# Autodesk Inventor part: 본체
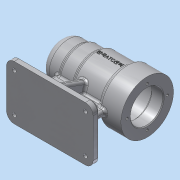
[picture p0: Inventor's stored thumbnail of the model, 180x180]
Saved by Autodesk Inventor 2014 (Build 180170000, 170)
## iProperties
Created: 2016-06
Part Number: 본체
Material: 알루미늄 6061
Document SubType Name: Modeling
Designer: 406-017
Density: 2.71 g/cm^3
Appearance: 알루미늄 - 평지
Mass: 624.755 g
Surface Area: 673.705 cm^2
Volume: 230.537 cm^3
Author: 406-017
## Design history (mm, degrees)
sketch "스케치1"
  geometry: L1 (0, 0)-(0, 25); L2 (0, 25)-(25, 25); L3 (25, 25)-(25, 27); L4 (25, 27)-(45, 27); L5 (45, 27)-(45, 30); L6 (45, 30)-(84, 30); L7 (84, 30)-(84, 34); L8 (84, 34)-(112, 34); L9 (112, 34)-(112, 0); L10 (112, 0)-(0, 0)
  constraints: 20 end point, 6 parallel, 2 perpendicular, 2 vertical
  dimensions: "d0" = 112 distance between parallel lines of L9 L1; "d1" = 50 diameter of L2 L10; "d2" = 54 diameter of L4 L10; "d4" = 60 diameter of L6 L10; "d5" = 68 diameter of L8 L10; "d6" = 25 distance of L1.end L2.end; "d7" = 45 distance between parallel lines of L5 L1; "d8" = 84 distance between parallel lines of L7 L1
revolve "회전1" sketch "스케치1" stored, may be unused: angle "d9" = 90 deg
sketch "스케치2"
  geometry: L1 (25, -25)-(0, -25) reference; L2 (0, -25)-(0, 25) reference; L3 (0, 25)-(25, 25) reference; L4 (25, 25)-(25, 27) reference; L5 (25, 27)-(45, 27) reference; L6 (45, 27)-(45, 30) reference; L7 (45, 30)-(84, 30) reference; L8 (84, 30)-(84, 34) reference; L9 (84, 34)-(112, 34) reference; L10 (112, 34)-(112, -34) reference; L11 (112, -34)-(84, -34) reference; L12 (84, -34)-(84, -30) reference; L13 (84, -30)-(45, -30) reference; L14 (45, -30)-(45, -27) reference; L15 (45, -27)-(25, -27) reference; L16 (25, -27)-(25, -25) reference; L17 (0, 0)-(112, 0); L18 (6, 0)-(6, 10.5); L19 (6, 10.5)-(9, 10.5); L20 (9, 10.5)-(9, 15.7); L21 (9.3, 16)-(13, 16); L22 (13, 16)-(13, 17.2); L23 (13.3, 17.5)-(31, 17.5); L24 (31, 17.5)-(31, 20.7); L25 (31.3, 21)-(43, 21); L26 (43, 21)-(43, 21); L27 (46, 24)-(94, 24); L28 (97, 21)-(97, 21); L29 (97, 21)-(112, 21); L30 (112, 0)-(112, 21); A1 r 0.3 centre (9.3, 15.7) between (9.3, 16) and (9, 15.7); A2 r 0.3 centre (13.3, 17.2) between (13.3, 17.5) and (13, 17.2); A3 r 0.3 centre (31.3, 20.7) between (31.3, 21) and (31, 20.7); A4 r 3 centre (46, 21) between (46, 24) and (43, 21); A5 r 3 centre (94, 21) between (97, 21) and (94, 24); 5 further points
  constraints: 28 end point, 12 point on line, 10 point on circle, 10 tangent, 6 perpendicular, 5 centre point, 5 parallel, 2 equal radius, 1 collinear, 1 midpoint, 1 vertical
  dimensions: "d10" = 15 distance of L28.end L29.end; "d11" = 54 distance of point (43, 24) point (97, 24); "d12" = 42 diameter of L29 L17; "d13" = 48 diameter of L27 L17; "d14" = 12 distance of point (31, 21) L25.end; "d15" = 18 distance of point (13, 17.5) L23.end; "d16" = 4 distance of point (9, 16) L21.end; "d17" = 3 distance of L18.end L19.end; "d18" = 42 diameter of L25 L17; "d19" = 35 diameter of L23 L17; "d20" = 32 diameter of L21 L17; "d21" = 21 diameter of L19 L17; "d22" = 0.3 radius of A1; "d50" = 3 radius of A4; "d85" = 3 radius of A5
revolve "회전2" sketch "스케치2" stored, may be unused: angle "d23" = 90 deg
node "작업 평면1"
sketch "스케치3"
  geometry: L1 (-112, -35)-(0, -35); L2 (0, -35)-(0, 35); L3 (0, 35)-(-112, 35); L4 (-112, 35)-(-112, -35); L5 (-112, -35)-(0, 35); L6 (0, -35)-(-112, 35); 2 further points
  constraints: 12 end point, 2 midpoint, 2 parallel, 1 horizontal, 1 perpendicular, 1 vertical alignment
  dimensions: "d25" = 112 distance of L2.end L3.end; "d26" = 70 distance of L1.end L2.end; "d27" = 35 distance from line of point (0, 0) L3
extrude "돌출1" join sketch "스케치3" distance "d28" = 10; taper "d29" = 0 deg
sketch "스케치4"
  geometry: L1 (92, -34)-(92, -60); L2 (92, -60)-(20, -60); L3 (20, -60)-(20, -27); L4 (20, -27)-(92, -60); L5 (92, -27)-(20, -60); L6 (112, -70)-(112, -60) reference; L7 (25, -25)-(0, -25) reference; L8 (0, -25)-(0, 25) reference; L9 (0, 25)-(25, 25) reference; L10 (25, 25)-(25, 27) reference; L11 (25, 27)-(45, 27) reference; L12 (45, 27)-(45, 30) reference; L13 (45, 30)-(84, 30) reference; L14 (84, 30)-(84, 34) reference; L15 (84, 34)-(112, 34) reference; L16 (112, 34)-(112, 21) reference; L17 (112, 21)-(97, 21) reference; L18 (94, 24)-(46, 24) reference; L19 (43, 21)-(31.3, 21) reference; L20 (31, 20.7)-(31, 17.5) reference; L21 (31, 17.5)-(13.3, 17.5) reference; L22 (13, 17.2)-(13, 16) reference; L23 (13, 16)-(9.3, 16) reference; L24 (9, 15.7)-(9, 10.5) reference; L25 (9, 10.5)-(6, 10.5) reference; L26 (6, 10.5)-(6, -10.5) reference; L27 (6, -10.5)-(9, -10.5) reference; L28 (9, -10.5)-(9, -15.7) reference; L29 (9.3, -16)-(13, -16) reference; L30 (13, -16)-(13, -17.2) reference; L31 (13.3, -17.5)-(31, -17.5) reference; L32 (31, -17.5)-(31, -20.7) reference; L33 (31.3, -21)-(43, -21) reference; L34 (46, -24)-(94, -24) reference; L35 (97, -21)-(112, -21) reference; L36 (112, -21)-(112, -34) reference; L37 (112, -34)-(84, -34) reference; L38 (84, -34)-(84, -30) reference; L39 (84, -30)-(45, -30) reference; L40 (45, -30)-(45, -27) reference; L41 (45, -27)-(25, -27) reference; L42 (25, -27)-(25, -25) reference; L43 (0, -70)-(0, -60) reference; L44 (0, -60)-(112, -60) reference; L45 (112, -60)-(112, -70) reference; L46 (112, -70)-(0, -70) reference; L47 (20, -27)-(20, -25); L48 (20, -25)-(20, -22); L49 (20, -22)-(41.379, -22); L50 (92, -27)-(92, -34); L51 (41.379, -22)-(45.428, -27); L52 (92, -27)-(45.428, -27); A1 r 0.3 centre (31.3, 20.7) between (31.3, 21) and (31, 20.7) reference; A2 r 0.3 centre (13.3, 17.2) between (13.3, 17.5) and (13, 17.2) reference; A3 r 0.3 centre (9.3, 15.7) between (9.3, 16) and (9, 15.7) reference; A4 r 0.3 centre (9.3, -15.7) between (9, -15.7) and (9.3, -16) reference; A5 r 0.3 centre (13.3, -17.2) between (13, -17.2) and (13.3, -17.5) reference; A6 r 0.3 centre (31.3, -20.7) between (31, -20.7) and (31.3, -21) reference; A7 r 3 centre (46, 21) between (46, 24) and (43, 21) reference; A8 r 3 centre (46, -21) between (43, -21) and (46, -24) reference; A9 r 3 centre (94, 21) between (97, 21) and (94, 24) reference; A10 r 3 centre (94, -21) between (94, -24) and (97, -21) reference; 3 further points
  constraints: 22 end point, 3 point on line, 2 horizontal alignment, 2 midpoint, 2 perpendicular, 1 collinear, 1 parallel, 1 vertical alignment
  dimensions: "d30" = 56 distance from line of point (56, -43.5) L6; "d31" = 20 distance between parallel lines of L1 L6; "d92" = 20 distance between parallel lines of L3 L43; "d95" = 38 distance between parallel lines of L2 L49; "d97" = 129 deg angle of L52 L51; "d98" = 90 deg angle of L50 L52; "d99" = 21.3788 distance of L48.end L49.end; "d100" = 38 distance from line of L44 L49.end; "d101" = 46.57228 distance of L50.start L51.end
extrude "돌출2" join sketch "스케치4" stored distance "d34" = 8; taper "d35" = 0 deg
node "작업 평면2"
sketch "스케치5"
  geometry: L1 (35, -60)-(35, -70) reference; L2 (35, -70)-(-35, -70) reference; L3 (-35, -70)-(-35, -60) reference; L4 (-35, -60)-(-4, -60) reference; L5 (-4, -60)-(-4, -29.732) reference; L6 (4, -29.732)-(4, -60) reference; L7 (4, -60)-(35, -60) reference; L8 (-28, -60)-(-15.509, -25.68); C1 r 24 at (0, 0) reference; A1 r 30 centre (0, 0) between (4, -29.732) and (-4, -29.732) reference; 1 further point
  constraints: 2 end point, 1 point on circle, 1 point on line
  dimensions: "d37" = 7 distance from line of L8.start L3; "d39" = 110 deg angle of L4 L8
feature "리브1" sketch "스케치5" dims "d40" = 1, "d41" = 8, "d42" = 0, "d43" = 0, "d44" = 1, "d45" = 1
fillet "모깎기1" dims "d46" = 10
chamfer "모따기1" distance "d47" = 4; stored, may be unused: second distance "d48" = 2, angle "d49" = 45 deg
hole "구멍1" diameter "d53" = 5; stored, may be unused: countersink angle "d57" = 90 deg, drill point angle "d59" = 118 deg; dims "d51" = 10, "d52" = 10, "d54" = 6, "d55" = 9, "d56" = 4, "d58" = 8
sketch "스케치6" dims "d66" = 52
  geometry: C1 r 21 at (0, 0) reference; C2 r 34 at (0, 0) reference; 2 further points
  constraints: 2 vertical alignment, 1 coincident, 2 other
hole "구멍2" sketch "스케치6" at (0, 26) diameter "d67" = 3.242; stored, may be unused: countersink angle "d71" = 90 deg, drill point angle "d73" = 118 deg; dims "d68" = 8, "d69" = 9, "d70" = 4, "d72" = 11
node "작업 평면3"
sketch "스케치7"
  geometry: L1 (47.5, -34)-(47.5, 34) reference; L2 (-17.03, 2.456)-(16.153, 2.456); L3 (16.153, 2.456)-(16.153, -2.347); L4 (16.153, -2.347)-(-17.03, -2.347); L5 (-17.03, -2.347)-(-17.03, 2.456); 2 further points
  constraints: 1 horizontal alignment, 2 other
  dimensions: "d77" = 48 distance from line of point (-0.5, 0) L1
feature "엠보싱1" sketch "스케치7" dims "d78" = 0.5, "d79" = 0
fillet "모깎기2" dims "d80" = 3, "d81" = 3
fillet "모깎기5" dims "d84" = 3
chamfer "모따기2" distance "d86" = 1; stored, may be unused: second distance "d87" = 2, angle "d88" = 45 deg
fillet "모깎기8" dims "d102" = 3
fillet "모깎기9" dims "d103" = 3
fillet "모깎기10" dims "d104" = 3
node "솔리드1"
mirror "대칭1"
pattern_linear "직사각형 패턴1" dims "d62" = 92
pattern_circular "원형 패턴1" dims angle "d75" = 360 deg
node "절단 모서리 투영1"
node "절단 모서리 투영2"
node "절단 모서리 투영3"
other parameters: "d36" = -56
